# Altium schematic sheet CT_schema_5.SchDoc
size 582 x 363 mm
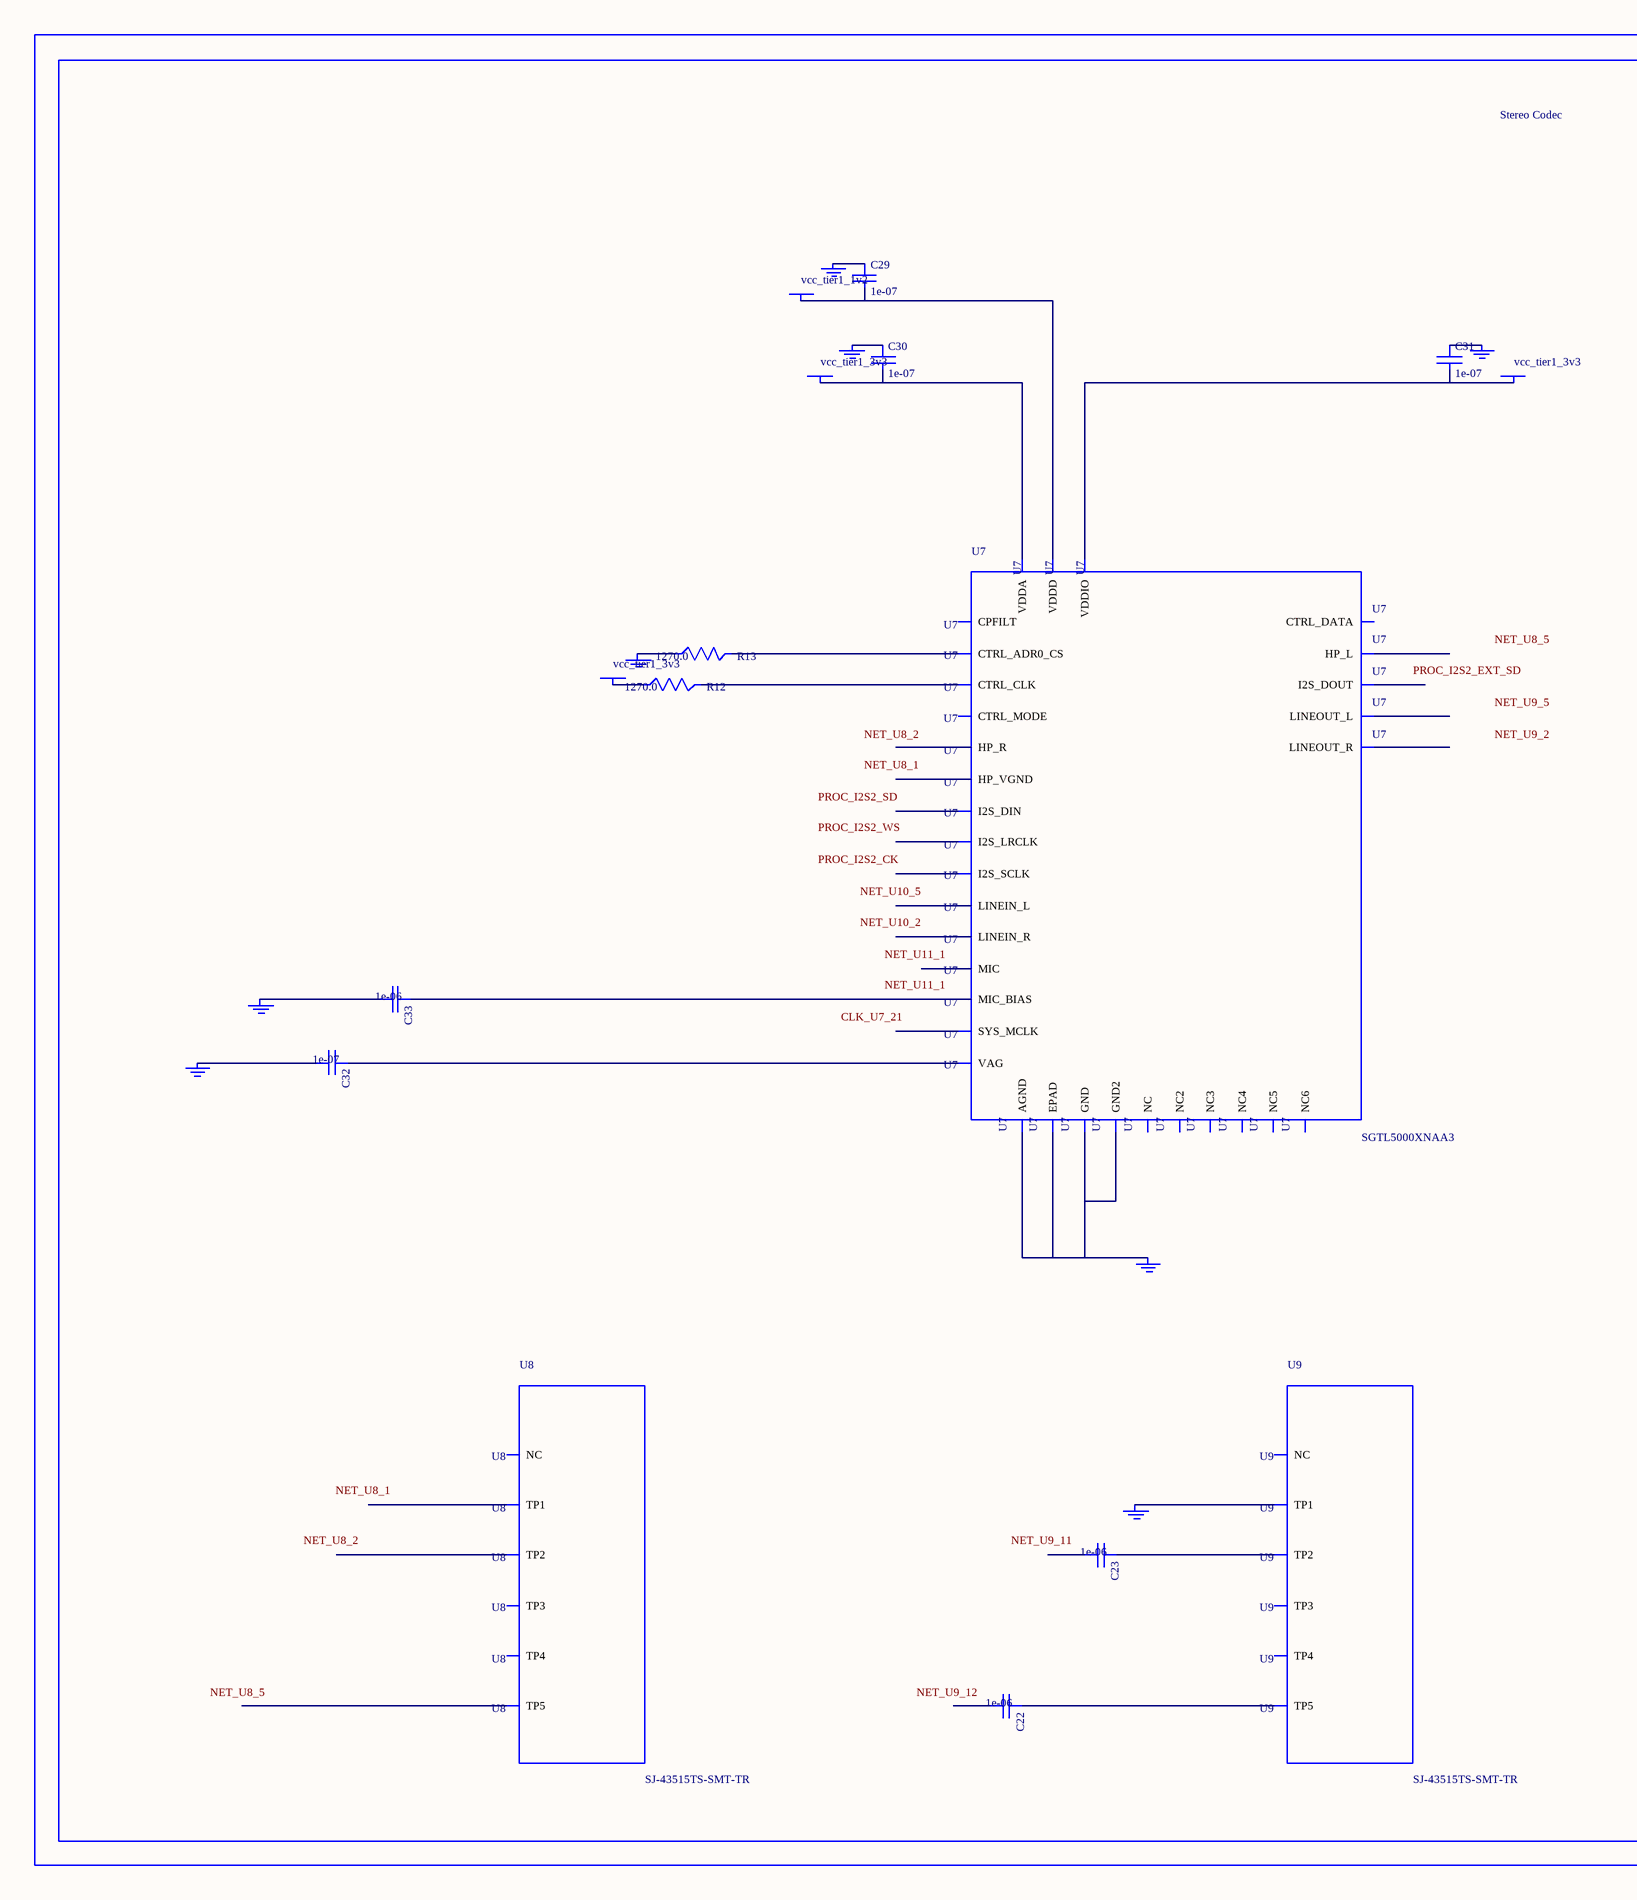
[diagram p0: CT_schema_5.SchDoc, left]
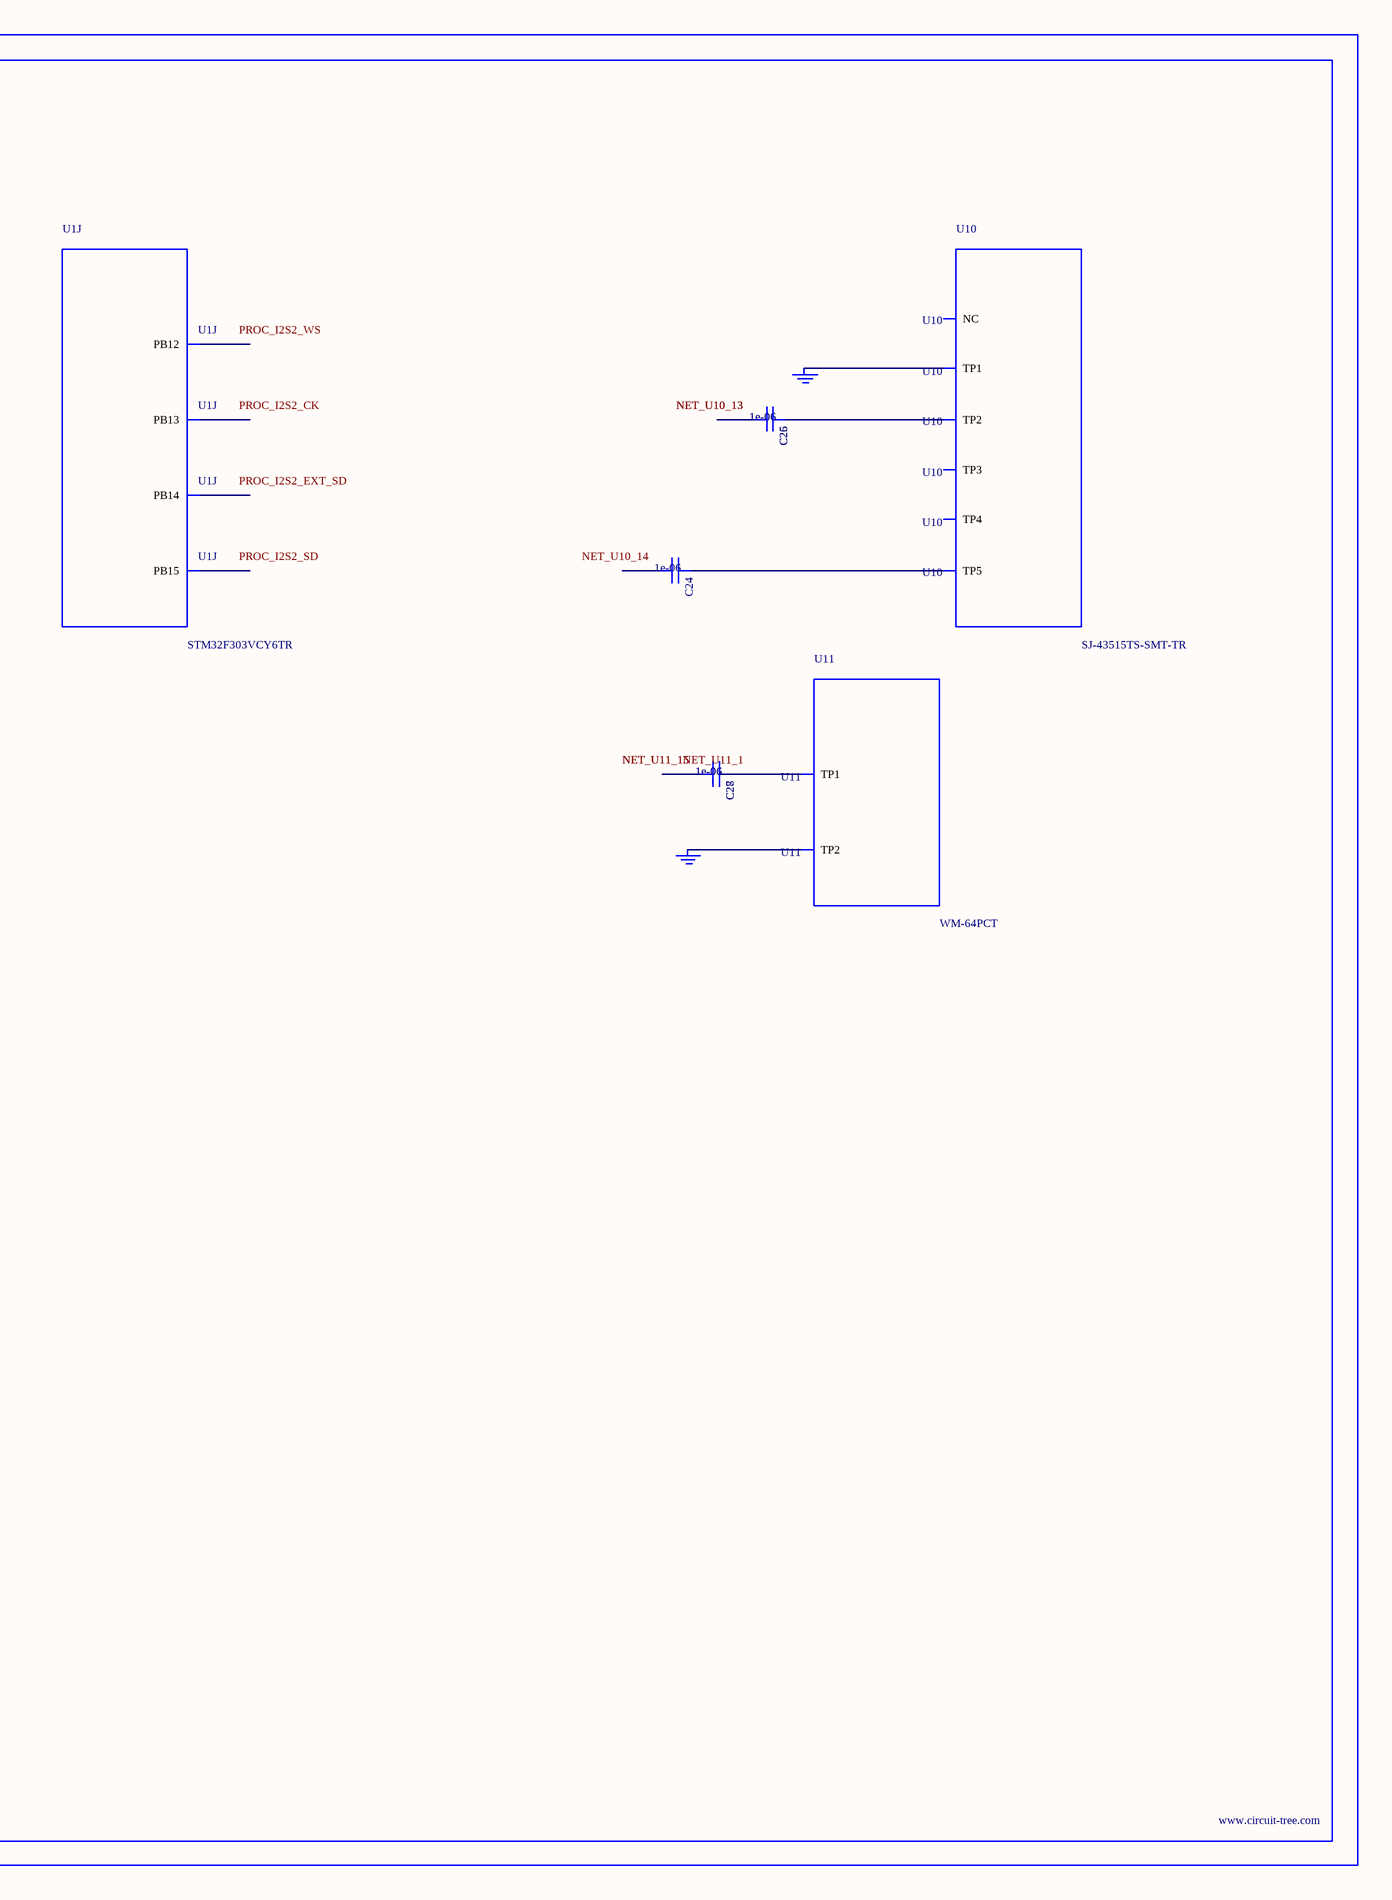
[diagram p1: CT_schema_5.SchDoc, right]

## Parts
BORDER4  (no value)
C22  1e-06  [C0603]
C23  1e-06  [C0603]
C24  1e-06  [C0603]
C25  1e-06  [C0603]
C26  1e-06  [C0603]
C27  1e-06  [C0603]
C28  1e-06  [C0603]
C29  1e-07  [C0402]
C30  1e-07  [C0402]
C31  1e-07  [C0402]
C32  1e-07  [C0402]
C33  1e-06  [C0603]
GND_INSTANCE_4_0  (no value)
GND_INSTANCE_4_1  (no value)
GND_INSTANCE_4_2  (no value)
GND_INSTANCE_4_3  (no value)
GND_INSTANCE_4_4  (no value)
GND_INSTANCE_4_5  (no value)
GND_INSTANCE_4_6  (no value)
GND_INSTANCE_4_7  (no value)
GND_INSTANCE_4_8  (no value)
GND_INSTANCE_4_9  (no value)
GND_INSTANCE_4_10  (no value)
POWER_INSTANCE_4_0  vcc_tier1_3v3
POWER_INSTANCE_4_1  vcc_tier1_3v3
POWER_INSTANCE_4_2  vcc_tier1_3v3
POWER_INSTANCE_4_3  vcc_tier1_1v2
R12  1270.0  [R0603]
R13  1270.0  [R0603]
U1  STM32F303VCY6TR  [WLCSP100]  (part J of 10)
U7  SGTL5000XNAA3  [QFN-32]
U8  SJ-43515TS-SMT-TR  [SJ-43515TS-SMT-TR]
U9  SJ-43515TS-SMT-TR  [SJ-43515TS-SMT-TR]
U10  SJ-43515TS-SMT-TR  [SJ-43515TS-SMT-TR]
U11  WM-64PCT  [WM-64PC]

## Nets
NetC22_1: C22.1 U9.5(TP5)
NetC23_1: C23.1 U9.2(TP2)
NetC24_1: C24.1 U10.5(TP5)
NetC25_1: C25.1 C26.1 U10.2(TP2)
NetC25_2: C25.2 C26.2
NetC27_1: C27.1 C28.1 U11.1(TP1)
NetC27_2: C27.2 C28.2
NetC29_1: C29.1 GND_INSTANCE_4_5.0(GND)
NetC29_2: C29.2 POWER_INSTANCE_4_3.0(PWR) U7.30(VDDD)
NetC30_1: C30.1 GND_INSTANCE_4_1.0(GND)
NetC30_2: C30.2 POWER_INSTANCE_4_0.0(PWR) U7.5(VDDA)
NetC31_1: C31.1 GND_INSTANCE_4_4.0(GND)
NetC31_2: C31.2 POWER_INSTANCE_4_1.0(PWR) U7.20(VDDIO)
NetC32_1: C32.1 U7.10(VAG)
NetC32_2: C32.2 GND_INSTANCE_4_2.0(GND)
NetC33_1: C33.1 U7.16(MIC_BIAS)
NetC33_2: C33.2 GND_INSTANCE_4_3.0(GND)
NetGND_INSTANCE_4_0_0: GND_INSTANCE_4_0.0(GND) U7.1(GND) U7.3(GND2) U7.7(AGND) U7.EXP(EPAD)
NetGND_INSTANCE_4_6_0: GND_INSTANCE_4_6.0(GND) R13.1
NetGND_INSTANCE_4_7_0: GND_INSTANCE_4_7.0(GND) U9.1(TP1)
NetGND_INSTANCE_4_8_0: GND_INSTANCE_4_8.0(GND) GND_INSTANCE_4_9.0(GND) U10.1(TP1)
NetGND_INSTANCE_4_10_0: GND_INSTANCE_4_10.0(GND) U11.2(TP2)
NetPOWER_INSTANCE_4_2_0: POWER_INSTANCE_4_2.0(PWR) R12.1
NetR12_2: R12.2 U7.29(CTRL_CLK)
NetR13_2: R13.2 U7.31(CTRL_ADR0_CS)

Not connected (* = marked no-connect by the designer): C22 2; C23 2; C24 2; U1 H4(PB15) J2(PB14) J3(PB13) J4(PB12); U7 2(HP_R) 4(HP_VGND) 6(HP_L) 8(NC) 9(NC2) 11(LINEOUT_R) 12(LINEOUT_L) 13(LINEIN_R) 14(LINEIN_L) 15(MIC) 17(NC3) 18(CPFILT) 19(NC4) 21(SYS_MCLK) 22(NC5) 23(I2S_LRCLK) 24(I2S_SCLK) 25(I2S_DOUT) 26(I2S_DIN) 27(CTRL_DATA) 28(NC6) 32(CTRL_MODE); U8 1(TP1) 2(TP2) 3(TP3) 4(TP4) 5(TP5) 6(NC); U9 3(TP3) 4(TP4) 6(NC); U10 3(TP3) 4(TP4) 6(NC)

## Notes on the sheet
- Labels drawn without touching a wire or pin: CLK_U7_21, NET_U8_1, NET_U8_2, NET_U8_5, NET_U9_2, NET_U9_5, NET_U9_11, NET_U9_12, NET_U10_2, NET_U10_5, NET_U10_14, NET_U11_1, PROC_I2S2_CK, PROC_I2S2_EXT_SD, PROC_I2S2_SD, PROC_I2S2_WS

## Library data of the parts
BORDER4 = BORDER_PAGE4
C22-C28 C33 = C0603C105K3RACTU
C29-C32 = C0402C104K3RACTU
GND_INSTANCE_4_0-GND_INSTANCE_4_10 = GND
POWER_INSTANCE_4_0-POWER_INSTANCE_4_3 = PWR
R12 R13 = RC0603FR-071K27L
